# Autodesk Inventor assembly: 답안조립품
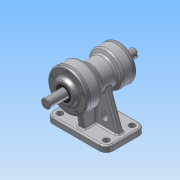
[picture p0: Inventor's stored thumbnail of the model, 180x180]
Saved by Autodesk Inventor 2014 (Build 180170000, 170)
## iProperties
Created: 2015-08
Part Number: 답안조립품
Document SubType Name: Assembly
Designer: study
Author: study
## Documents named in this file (10)
- C:\Users\study\Desktop\450805V1022\답안조립품.iam
- C:\Users\study\Desktop\450805V1022\1-본체.ipt
- C:\Users\study\Desktop\450805V1022\베어링 6203.ipt
- C:\Users\study\Desktop\450805V1022\베어링 6205.ipt
- C:\Users\study\Desktop\450805V1022\뒤커버.ipt
- C:\Users\study\Desktop\450805V1022\앞커버.ipt
- C:\Users\study\Desktop\450805V1022\오일실 .ipt
- 오일실 .ipt
- C:\Users\study\Desktop\450805V1022\축.ipt
- C:\Users\study\Desktop\450805V1022\M4x0.5.ipt
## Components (11 placed, 2 different names)
1. 1-본체:1
2. M4x0.5:2
3. M4x0.5:3
4. M4x0.5:4
5. M4x0.5:5
6. M4x0.5:6
7. M4x0.5:1
8. M4x0.5:7
9. M4x0.5:8
10. M4x0.5:9
11. M4x0.5:10
